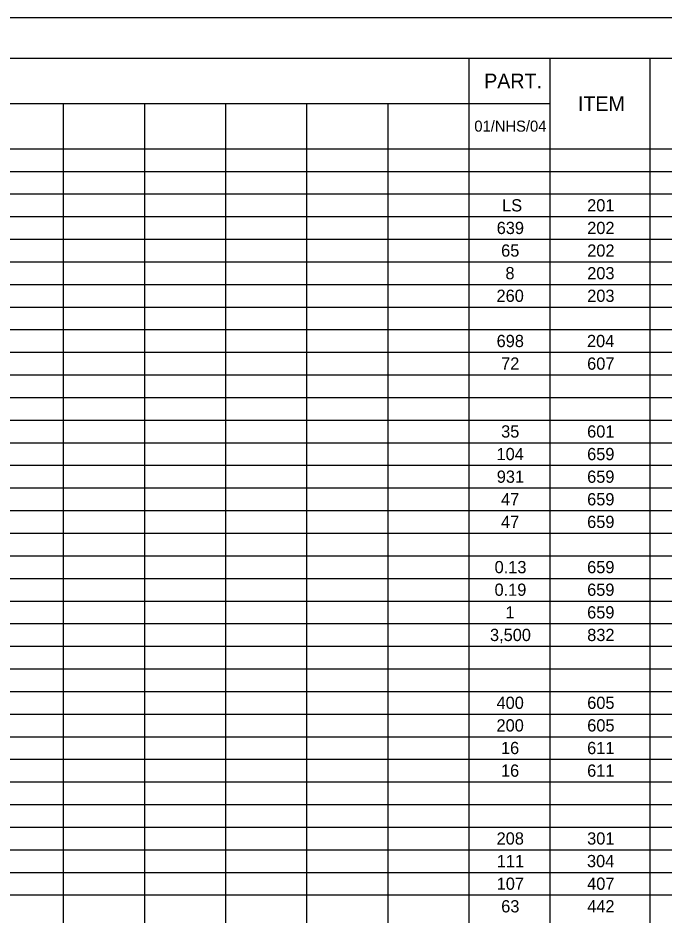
# Model space of a CAD drawing. Extents: x 0 to 34, y 0 to 22.
# Drawn here: x 8.98 to 16.98, y 10.89 to 22 of the extents above; entities that cross this region are included whole.
import ezdxf

# ---------------------------------------------------------------- set-up
doc = ezdxf.new("R2010")
doc.units = 0
for name, color, linetype in [('Default', 7, 'Continuous'), ('SH_Border', 7, 'Continuous'), ('SH_Cut_Line', 7, 'Continuous')]:
    doc.layers.add(name, color=color, linetype=linetype)

msp = doc.modelspace()

# ---------------------------------------------------------------- linework, layer by layer
at = {"layer": 'Default'}
for p, q in [((1.5, 21.5), (32, 21.5)), ((14.56, 21.5), (14.56, 0.5)), ((15.564, 21.5), (15.564, 0.5)), ((16.799, 21.5), (16.799, 0.5)), ((1.5, 20.94), (15.564, 20.94)), ((9.537, 20.94), (9.537, 0.5)), ((10.541, 20.94), (10.541, 0.5)), ((11.546, 20.94), (11.546, 0.5)), ((12.55, 20.94), (12.55, 0.5)), ((13.555, 20.94), (13.555, 0.5)), ((1.5, 20.38), (32, 20.38)), ((1.5, 20.1), (32, 20.1)), ((1.5, 19.82), (32, 19.82)), ((1.5, 19.54), (32, 19.54)), ((1.5, 19.26), (32, 19.26)), ((1.5, 18.98), (32, 18.98)), ((1.5, 18.7), (32, 18.7)), ((1.5, 18.42), (32, 18.42)), ((1.5, 18.14), (32, 18.14)), ((1.5, 17.86), (32, 17.86)), ((1.5, 17.58), (32, 17.58)), ((1.5, 17.3), (32, 17.3)), ((1.5, 17.02), (32, 17.02)), ((1.5, 16.74), (32, 16.74)), ((1.5, 16.46), (32, 16.46)), ((1.5, 16.18), (32, 16.18)), ((1.5, 15.9), (32, 15.9)), ((1.5, 15.62), (32, 15.62)), ((1.5, 15.34), (32, 15.34)), ((1.5, 15.06), (32, 15.06)), ((1.5, 14.78), (32, 14.78)), ((1.5, 14.5), (32, 14.5)), ((1.5, 14.22), (32, 14.22)), ((1.5, 13.94), (32, 13.94)), ((1.5, 13.66), (32, 13.66)), ((1.5, 13.38), (32, 13.38)), ((1.5, 13.1), (32, 13.1)), ((1.5, 12.82), (32, 12.82)), ((1.5, 12.54), (32, 12.54)), ((1.5, 12.26), (32, 12.26)), ((1.5, 11.98), (32, 11.98)), ((1.5, 11.7), (32, 11.7)), ((1.5, 11.42), (32, 11.42)), ((1.5, 11.14), (32, 11.14))]:
    msp.add_line(p, q, dxfattribs=at)
at = {"layer": 'SH_Border'}
msp.add_lwpolyline([(1.5, 21.5), (33.5, 21.5), (33.5, 0.5), (1.5, 0.5)], close=True, dxfattribs=at)
at = {"layer": 'SH_Cut_Line'}
msp.add_lwpolyline([(0, 0), (34, 0), (34, 22), (0, 22)], close=True, dxfattribs=at)

# ---------------------------------------------------------------- texts
at = {"layer": 'Default'}
for s, height, p in [('PART.', 0.1818, (14.749, 21.129)), ('ITEM', 0.1818, (15.91, 20.849)), ('01/NHS/04', 0.1364, (14.627, 20.592)), ('LS', 0.1515, (14.971, 19.604)), ('201', 0.1515, (16.024, 19.604)), ('639', 0.1515, (14.904, 19.324)), ('202', 0.1515, (16.025, 19.324)), ('65', 0.1515, (14.959, 19.044)), ('202', 0.1515, (16.025, 19.044)), ('8', 0.152, (15.012, 18.764)), ('203', 0.1515, (16.025, 18.764)), ('260', 0.1515, (14.902, 18.484)), ('203', 0.1515, (16.025, 18.484)), ('698', 0.1515, (14.903, 17.924)), ('204', 0.1515, (16.022, 17.924)), ('72', 0.1515, (14.959, 17.644)), ('607', 0.1515, (16.024, 17.644)), ('35', 0.1515, (14.959, 16.804)), ('601', 0.1515, (16.024, 16.804)), ('104', 0.1515, (14.902, 16.524)), ('659', 0.1515, (16.024, 16.524)), ('931', 0.1515, (14.905, 16.244)), ('659', 0.1515, (16.024, 16.244)), ('47', 0.1515, (14.958, 15.964)), ('659', 0.1515, (16.024, 15.964)), ('47', 0.1515, (14.958, 15.684)), ('659', 0.1515, (16.024, 15.684)), ('0.13', 0.1515, (14.878, 15.124)), ('659', 0.1515, (16.024, 15.124)), ('0.19', 0.1515, (14.877, 14.844)), ('659', 0.1515, (16.024, 14.844)), ('1', 0.152, (15.013, 14.564)), ('659', 0.1515, (16.024, 14.564)), ('3,500', 0.1515, (14.821, 14.284)), ('832', 0.1515, (16.025, 14.284)), ('400', 0.1515, (14.902, 13.444)), ('605', 0.1515, (16.025, 13.444)), ('200', 0.1515, (14.902, 13.164)), ('605', 0.1515, (16.025, 13.164)), ('16', 0.1515, (14.957, 12.884)), ('611', 0.1515, (16.024, 12.884)), ('16', 0.1515, (14.957, 12.604)), ('611', 0.1515, (16.024, 12.604)), ('208', 0.1515, (14.903, 11.764)), ('301', 0.1515, (16.024, 11.764)), ('111', 0.1515, (14.905, 11.484)), ('304', 0.1515, (16.022, 11.484)), ('107', 0.1515, (14.904, 11.204)), ('407', 0.1515, (16.024, 11.204)), ('63', 0.1515, (14.96, 10.924)), ('442', 0.1515, (16.025, 10.924))]:
    msp.add_text(s, height=height, dxfattribs=at).set_placement(p)

doc.saveas('drawing.dxf')
